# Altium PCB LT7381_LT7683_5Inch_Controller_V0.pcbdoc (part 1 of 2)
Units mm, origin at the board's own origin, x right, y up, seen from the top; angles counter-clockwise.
Board outline 60 x 56 mm, 2 copper layers (Top Layer, Bottom Layer); 80 components, 113 nets, 434 pads, 201 vias.
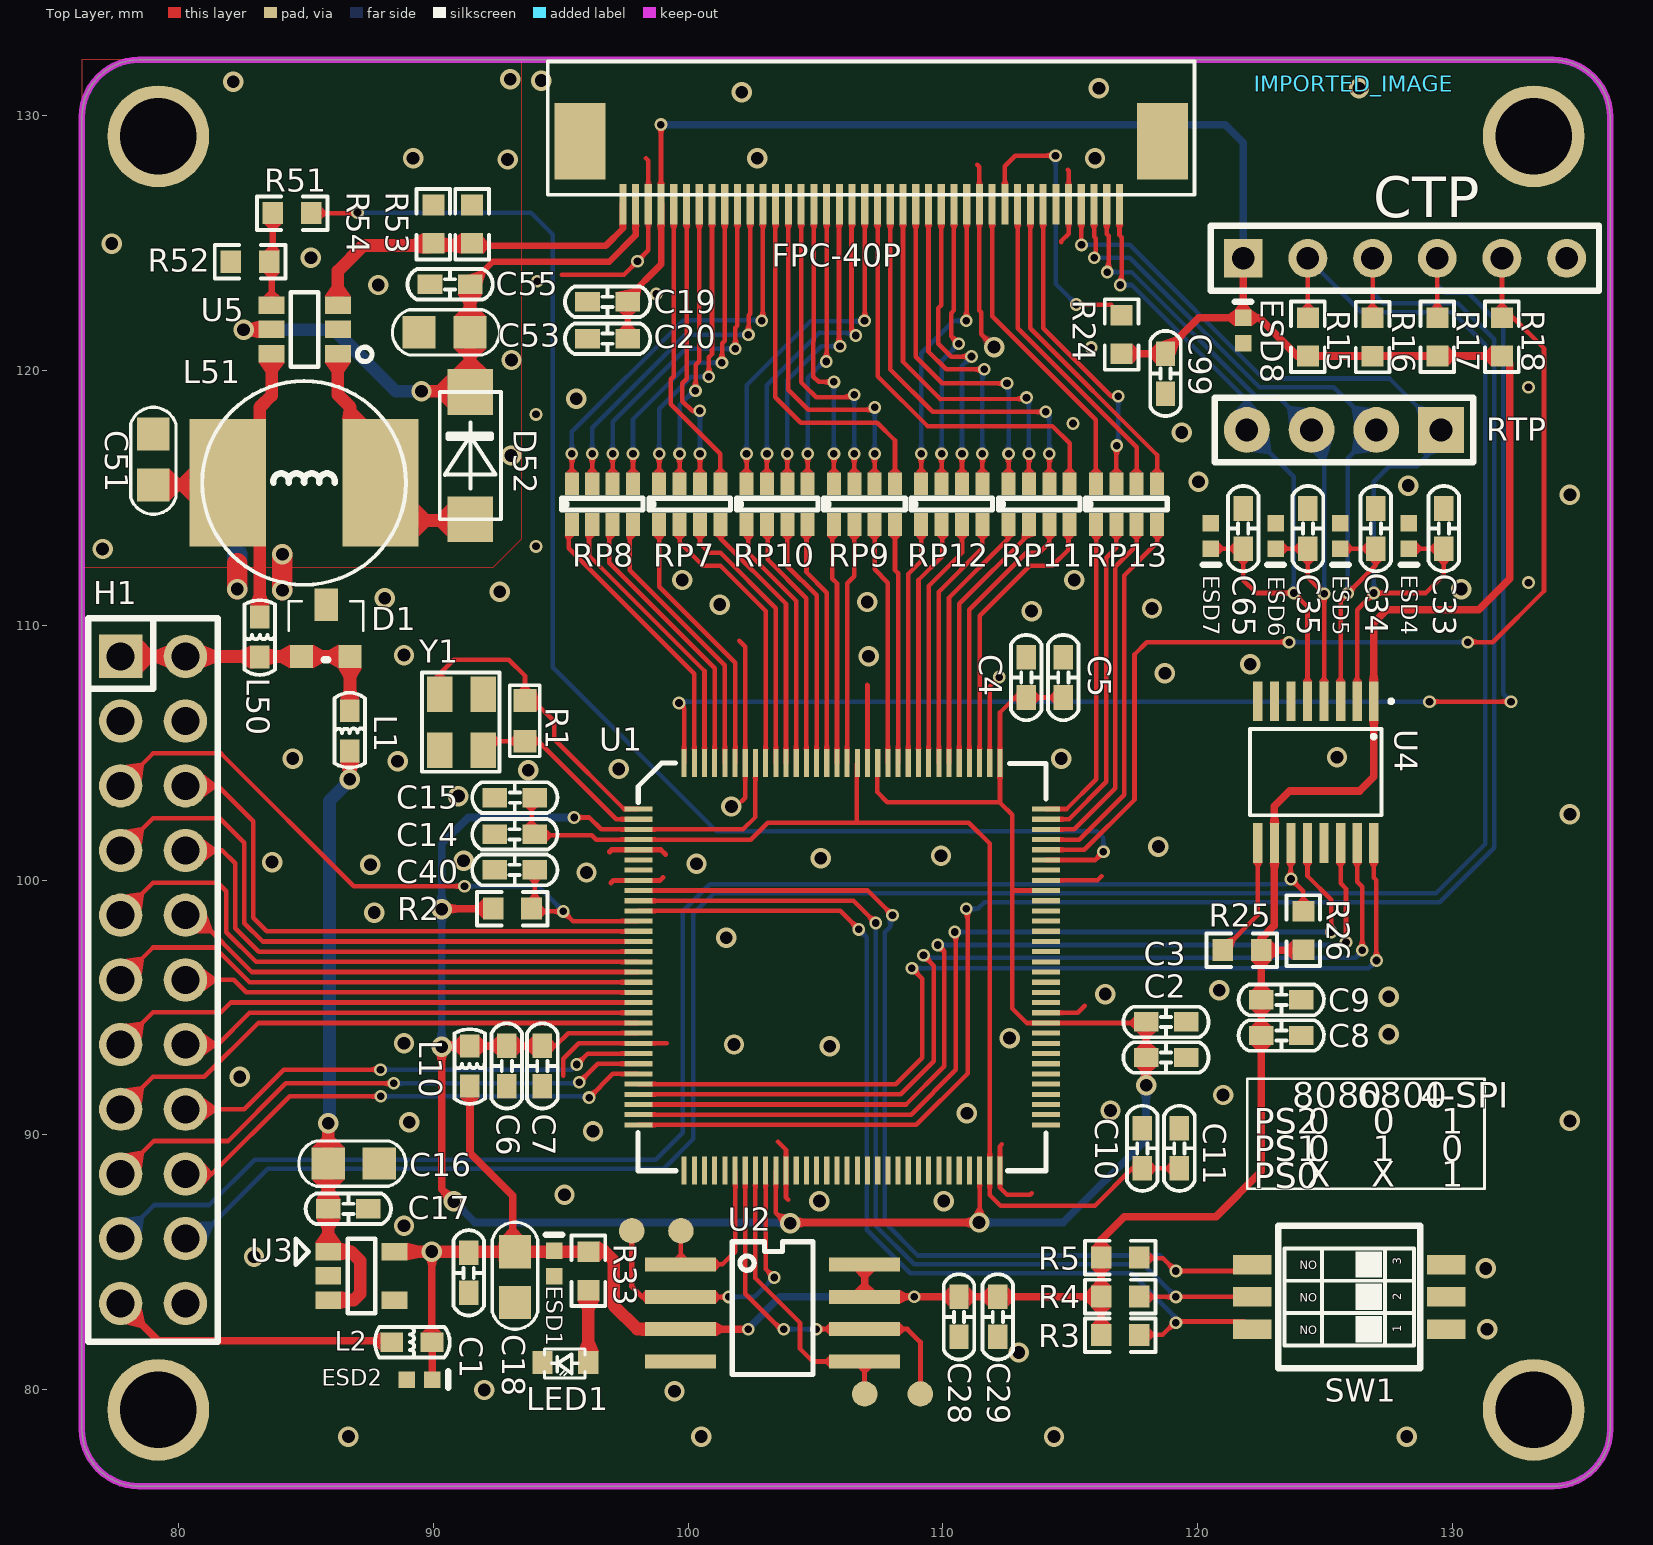
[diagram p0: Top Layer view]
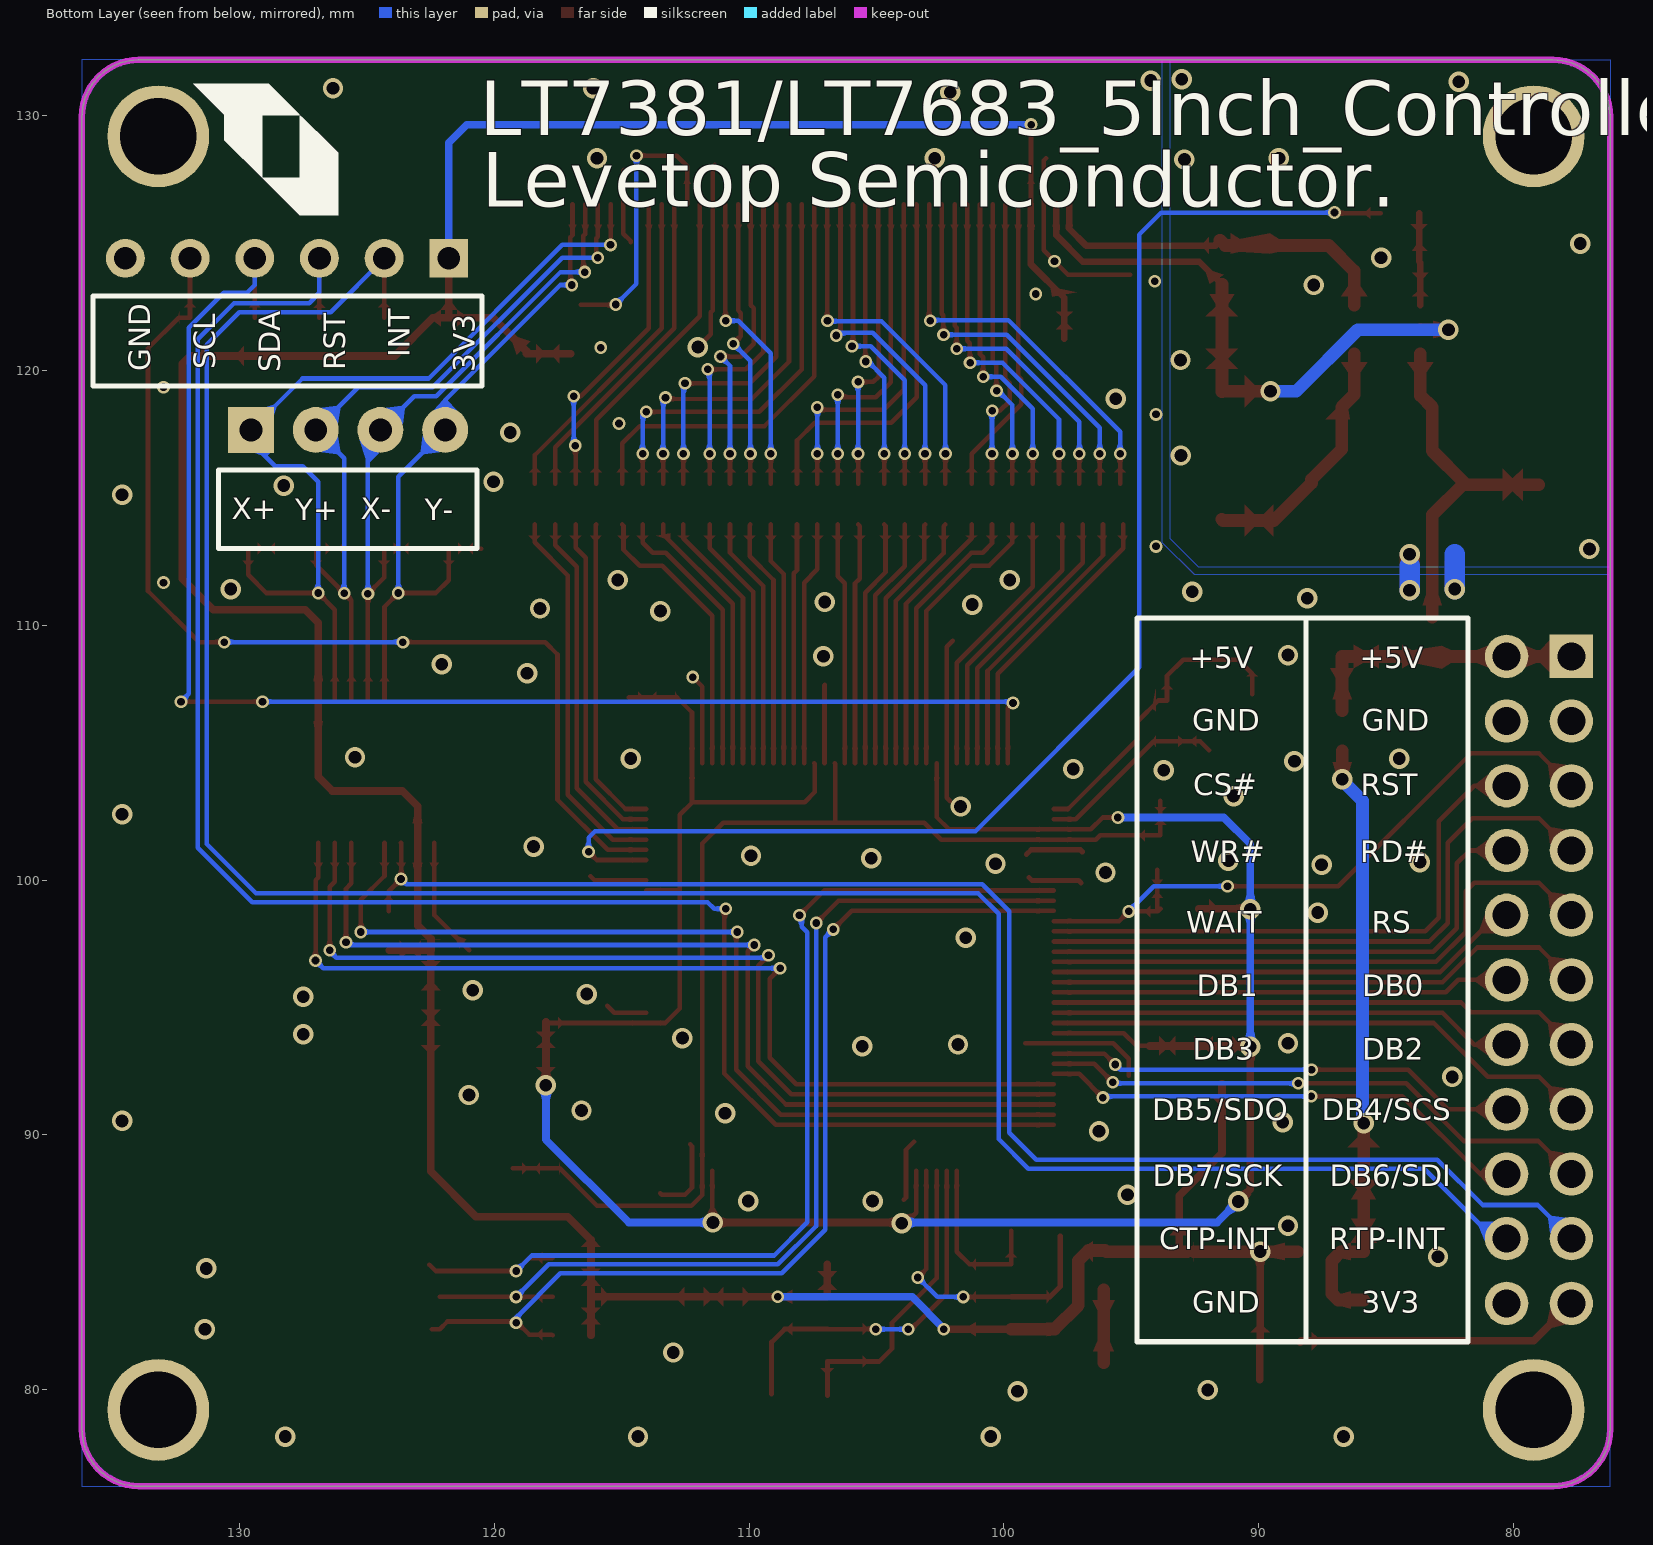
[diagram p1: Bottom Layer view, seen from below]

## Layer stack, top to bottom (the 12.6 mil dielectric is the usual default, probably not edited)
Top Layer: signal copper (thickness not stored)
Dielectric: dielectric 0.32, FR-4, Dk 4.8
Bottom Layer: signal copper (thickness not stored)

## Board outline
78.44,132.2 133.96,132.2 cw(c133.96,129.96) 136.2,129.96 136.2,78.44 cw(c133.96,78.44) 133.96,76.2 78.44,76.2 cw(c78.44,78.44) 76.2,78.44 76.2,129.96 cw(c78.44,129.96)

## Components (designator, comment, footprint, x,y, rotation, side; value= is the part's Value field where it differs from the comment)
C1 "1uF" C0603 91.389,85.362 r270 top
C2 "1uF" C0603 117.983,93.032 r0 top
C3 "0.1uf" C0603 117.983,94.429 r0 top
C4 "1uF" C0603 113.277,107.168 r90 top
C5 "0.1uf" C0603 114.731,107.168 r90 top
C6 "1uF" C0603 92.884,93.484 r270 top
C7 "0.1uf" C0603 94.281,93.484 r270 top
C8 "1uF" C0603 122.506,93.897 r0 top
C9 "0.1uF" C0603 122.506,95.294 r0 top
C10 "1uF" C0603 117.834,88.682 r90 top
C11 "0.1uf" C0603 119.288,88.682 r90 top
C14 "1uF" C0603 93.98,101.795 r180 top
C15 "0.1uf" C0603 93.981,103.236 r180 top
C16 "10uF" C0805 85.87,88.881 r0 top
C17 "1uF" C0603 85.878,87.092 r0 top
C18 "10uF" C0805 93.218,85.413 r270 top
C19 "1uF" C0603 97.625,122.7 r180 top
C20 "0.1uf" C0603 97.623,121.251 r180 top
C28 "1uF" C0603 110.638,83.634 r270 top
C29 "0.1uf" C0603 112.162,83.634 r270 top
C33 "20pF" C0603 129.669,113.014 r90 top
C34 "20pF" C0603 127.002,113.014 r90 top
C35 "20pF" C0603 124.335,113.014 r90 top
C40 "1uF" C0603 93.978,100.397 r180 top
C51 "22uF/50V" C0805_1 78.994,115.511 r90 top
C53 "22uF/50V" C0805_1 91.441,121.489 r180 top
C55 "0.1uF/50V" C0603 91.44,123.385 r180 top
C65 "20pF" C0603 121.795,113.014 r90 top
C99 "1uF" C0603 118.745,120.667 r270 top
CTP "HDR_6P" SIP-6P 121.793,124.409 r0 top
D1 "MMBZ5V6A" SOT-23 84.836,108.78 r0 top
D52 "B340A" DO-214 91.44,116.654 r90 top
ESD1 "PESD0402MS05" ESD0402 94.742,84.448 r90 top
ESD2 "PESD0402MS05" ESD0402 88.951,80.384 r0 top
ESD4 "PESD0402MS05" ESD0402 128.295,114.012 r270 top
ESD5 "PESD0402MS05" ESD0402 125.605,114.012 r270 top
ESD6 "PESD0402MS05" ESD0402 123.065,114.012 r270 top
ESD7 "PESD0402MS05" ESD0402 120.525,114.012 r270 top
ESD8 "PESD0402MS05" ESD0402 121.793,121.074 r90 top
FPC-40P "COM40" FPC40-0.5 107.188,126.687 r0 top
H1 "HDR_2*11P_2.54" HDR-TH_22P-P2.54-V-M-R2-C11-S2.54 78.994,96.08 r270 top
IMPORTED_IMAGE "IMPORTED_IMAGE" IMPORTED_IMAGE 126.136,131.267 r0 top
L1 "BEAD 0603 600R&amp;100MHZ" L0603 86.716,105.86 r270 top
L2 "BEAD 0603 600R&amp;100MHZ" L0603 89.154,81.857 r180 top
L10 "BEAD 0603 600R&amp;100MHZ" L0603 91.423,92.699 r90 top
L50 "BEAD 0603 600R&amp;100MHZ" L0603 83.185,109.542 r90 top
L51 "10uH 1A" IND8A 84.916,115.589 r0 top
LED1 "LED_1" 0603LED 96.085,81.056 r180 top
R1 "1M" R0603_1 93.597,107.049 r270 top
R2 "120R" R0603 93.1,98.874 r180 top
R3 "10K" R0603 116.967,82.129 r180 top
R4 "10K" R0603 116.967,83.648 r180 top
R5 "10K" R0603 116.967,85.177 r180 top
R15 "10K" R0603 124.333,121.328 r90 top
R16 "10K" R0603 126.873,121.32 r90 top
R17 "10K" R0603 129.413,121.328 r90 top
R18 "10K" R0603 131.953,121.328 r90 top
R24 "10K" R0603 117.018,121.418 r90 top
R25 "0R" R0603 121.742,97.245 r0 top
R26 "10K" R0603 124.155,98.016 r90 top
R33 "4.7K" R0603 96.085,84.656 r90 top
R51 "100R" R0603 84.455,126.179 r180 top
R52 "10K" R0603 82.804,124.274 r180 top
R53 "12R" R0603 89.996,125.749 r90 top
R54 "12R" R0603 91.52,125.749 r90 top
RP7 "RP4" 8R4R 100.076,114.749 r90 top
RP8 "RP4" 8R4R 96.647,114.749 r90 top
RP9 "RP4" 8R4R 106.934,114.749 r90 top
RP10 "RP4" 8R4R 103.505,114.749 r90 top
RP11 "RP4" 8R4R 113.792,114.749 r90 top
RP12 "RP4" 8R4R 110.363,114.749 r90 top
RP13 "RP4" 8R4R 117.221,114.749 r90 top
RTP "CON4" SIP-4P 129.558,117.67 r180 top
SW1 "DSHP03TSGET" SW-SMD_6P-L5.4-W5.4-P1.27-LS8.4 125.959,83.634 r90 top
U1 "LT768-136" LQFP128L 106.045,96.588 r90 top
U2 "XT25F128B/W25Q128B" SOP-8A 100.457,84.904 r0 top
U3 "HP5013 3-2" SOT23-5 85.879,85.417 r270 top
U4 "TSC2046" TSSOP-16_L5.0-W4.4-P0.65-LS6.4-BL-1 124.644,104.238 r180 top
U5 "HP2302D" SOT23-6 83.646,122.574 r90 top
Y1 "10M" M3225_1 91.95,105.099 r90 top

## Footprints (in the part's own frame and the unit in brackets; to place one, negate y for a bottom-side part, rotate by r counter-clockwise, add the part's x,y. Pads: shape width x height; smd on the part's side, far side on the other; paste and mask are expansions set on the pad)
8R4R [mm]
  rect 0.9x0.55 smd mask+0.102: 1(-0.79,1.209) 2(-0.79,0.409) 3(-0.79,-0.391) 4(-0.79,-1.191) 5(0.81,-1.191) 6(0.81,-0.391) 7(0.81,0.409) 8(0.81,1.209)
  silkscreen extent -0.22,-1.59 0.24,1.61
0603LED [mm]
  rect 0.8x0.9 smd mask+0.102: 1(0,0) 2(1.8,0)
  silkscreen extent 0.13,-0.53 1.73,0.6
C0603 [mil]
  rect 38x30 smd mask+4: 1(-0.09,-0.02) 2(61.91,-0.02)
  silkscreen extent -35,-24 97,24
C0805 [mm]
  rect 1.3x1.27 smd mask+0.102: 1(0.005,-0.011) 2(2.005,-0.011)
  silkscreen extent -1.15,-0.9 3.05,0.88
C0805_1 [mm]
  rect 1.3x1.27 smd mask+0.102: 1(0.005,-0.011) 2(2.005,-0.011)
  silkscreen extent -1.15,-0.9 3.05,0.88
DO-214 [mm]
  rect 1.8x1.8 smd mask+0.102: 1(-2.488,-0.011) 2(2.512,-0.011)
  silkscreen extent -2.49,-1.21 2.51,1.19
ESD0402 [mm]
  rect 0.65x0.65 smd mask+0.102: 1(1,0) 2(0,0)
  silkscreen extent 1.63,-0.32 1.63,0.33
FPC40-0.5 [mm]
  rect 0.28x1.6 smd mask+0.102: 1(-9.75,-0.159) 2(-9.25,-0.159) 3(-8.75,-0.159) 4(-8.25,-0.159) 5(-7.75,-0.159) 6(-7.25,-0.159) 7(-6.75,-0.159) 8(-6.25,-0.159) 9(-5.75,-0.159) 10(-5.25,-0.159) 11(-4.75,-0.159) 12(-4.25,-0.159) 13(-3.75,-0.159) 14(-3.25,-0.159) 15(-2.75,-0.159) 16(-2.25,-0.159) 17(-1.75,-0.159) 18(-1.25,-0.159) 19(-0.75,-0.159) 20(-0.25,-0.159) 21(0.25,-0.159) 22(0.75,-0.159) 23(1.25,-0.159) 24(1.75,-0.159) 25(2.25,-0.159) 26(2.75,-0.159) 27(3.25,-0.159) 28(3.75,-0.159) 29(4.25,-0.159) 30(4.75,-0.159) 31(5.25,-0.159) 32(5.75,-0.159) 33(6.25,-0.159) 34(6.75,-0.159) 35(7.25,-0.159) 36(7.75,-0.159) 37(8.25,-0.159) 38(8.75,-0.159) 39(9.25,-0.159) 40(9.75,-0.159)
  rect 2x3 smd mask+0.102: 41(-11.44,2.316) 42(11.44,2.316)
  silkscreen extent -12.7,0.22 12.7,5.45
HDR-TH_22P-P2.54-V-M-R2-C11-S2.54 [mm]
  rect 1.7x1.7 hole 1.1 paste+0 mask+0.051: 1(-12.7,-1.27)
  round 1.7 hole 1.1 paste+0 mask+0.051: 2(-12.7,1.27) 3(-10.16,-1.27) 4(-10.16,1.27) 5(-7.62,-1.27) 6(-7.62,1.27) 7(-5.08,-1.27) 8(-5.08,1.27) 9(-2.54,-1.27) 10(-2.54,1.27) 11(0,-1.27) 12(0,1.27) 13(2.54,-1.27) 14(2.54,1.27) 15(5.08,-1.27) 16(5.08,1.27) 17(7.62,-1.27) 18(7.62,1.27) 19(10.16,-1.27) 20(10.16,1.27) 21(12.7,-1.27) 22(12.7,1.27)
  silkscreen extent -14.2,-2.54 14.2,2.54
IMPORTED_IMAGE [mm]
IND8A [mm]
  rect 3x5 smd mask+0.102: 1(-2.992,0.003) 2(3.008,0.003)
  silkscreen extent -3.99,-4 4.01,4
L0603 [mil]
  rect 35.43x30 smd mask+4: 1(-31,0) 2(31,0)
  silkscreen extent -59,-24 57,24
LQFP128L [mm]
  rect 0.2x1.1 smd paste+0 mask+0.102: 1(6.2,8) 2(5.8,8) 3(5.4,8) 4(5,8) 5(4.6,8) 6(4.2,8) 7(3.8,8) 8(3.4,8) 9(3,8) 10(2.6,8) 11(2.2,8) 12(1.8,8) 13(1.4,8) 14(1,8) 15(0.6,8) 16(0.2,8) 17(-0.2,8) 18(-0.6,8) 19(-1,8) 20(-1.4,8) 21(-1.8,8) 22(-2.2,8) 23(-2.6,8) 24(-3,8) 25(-3.4,8) 26(-3.8,8) 27(-4.2,8) 28(-4.6,8) 29(-5,8) 30(-5.4,8) 31(-5.8,8) 32(-6.2,8) 65(-6.2,-8) 66(-5.8,-8) 67(-5.4,-8) 68(-5,-8) 69(-4.6,-8) 70(-4.2,-8) 71(-3.8,-8) 72(-3.4,-8) 73(-3,-8) 74(-2.6,-8) 75(-2.2,-8) 76(-1.8,-8) 77(-1.4,-8) 78(-1,-8) 79(-0.6,-8) 80(-0.2,-8) 81(0.2,-8) 82(0.6,-8) 83(1,-8) 84(1.4,-8) 85(1.8,-8) 86(2.2,-8) 87(2.6,-8) 88(3,-8) 89(3.4,-8) 90(3.8,-8) 91(4.2,-8) 92(4.6,-8) 93(5,-8) 94(5.4,-8) 95(5.8,-8) 96(6.2,-8)
  rect 1.1x0.2 smd paste+0 mask+0.102: 33(-8,6.2) 34(-8,5.8) 35(-8,5.4) 36(-8,5) 37(-8,4.6) 38(-8,4.2) 39(-8,3.8) 40(-8,3.4) 41(-8,3) 42(-8,2.6) 43(-8,2.2) 44(-8,1.8) 45(-8,1.4) 46(-8,1) 47(-8,0.6) 48(-8,0.2) 49(-8,-0.2) 50(-8,-0.6) 51(-8,-1) 52(-8,-1.4) 53(-8,-1.8) 54(-8,-2.2) 55(-8,-2.6) 56(-8,-3) 57(-8,-3.4) 58(-8,-3.8) 59(-8,-4.2) 60(-8,-4.6) 61(-8,-5) 62(-8,-5.4) 63(-8,-5.8) 64(-8,-6.2) 97(8,-6.2) 98(8,-5.8) 99(8,-5.4) 100(8,-5) 101(8,-4.6) 102(8,-4.2) 103(8,-3.8) 104(8,-3.4) 105(8,-3) 106(8,-2.6) 107(8,-2.2) 108(8,-1.8) 109(8,-1.4) 110(8,-1) 111(8,-0.6) 112(8,-0.2) 113(8,0.2) 114(8,0.6) 115(8,1) 116(8,1.4) 117(8,1.8) 118(8,2.2) 119(8,2.6) 120(8,3) 121(8,3.4) 122(8,3.8) 123(8,4.2) 124(8,4.6) 125(8,5) 126(8,5.4) 127(8,5.8) 128(8,6.2)
  silkscreen extent -8,-8.01 8,8.01
M3225_1 [mm]
  rect 1.4x1 smd mask+0.102: 1(0,0) 2(2.2,0) 3(2.2,1.7) 4(0,1.7)
  silkscreen extent -0.85,-0.65 3.05,2.4
R0603 [mm]
  rect 0.806x0.864 smd paste-100 mask+0.051: 1(-0.753,0) 2(0.753,0)
  silkscreen extent -1.39,-0.66 1.39,0.66
R0603_1 [mm]
  rect 0.9x0.9 smd mask+0.102: 1(0,0) 2(1.6,0)
  silkscreen extent -0.6,-0.6 2.2,0.58
SIP-4P [mm]
  rect 1.8x1.8 hole 0.889 mask+0.102: 1(0,0)
  round 1.8 hole 0.889 mask+0.102: 2(2.54,0) 3(5.08,0) 4(7.62,0)
  silkscreen extent -1.27,-1.27 8.89,1.27
SIP-6P [mil]
  rect 60x60 hole 35 mask+4: 1(0,0)
  round 60 hole 35 mask+4: 2(100,0) 3(200,0) 4(300,0) 5(400,0) 6(500,0)
  silkscreen extent -50,-50 550,50
SOP-8A [mm]
  rect 2.778x0.55 smd mask+0.102: 1(-0.75,0.005) 2(-0.75,-1.265) 3(-0.75,-2.535) 4(-0.75,-3.805) 5(6.473,-3.805) 6(6.473,-2.535) 7(6.473,-1.265) 8(6.473,0.005)
  silkscreen extent 1.27,-4.31 4.45,0.89
SOT23-5 [mil]
  rect 27x40 smd mask+4: 1(0.28,-0.14) 2(37.68,-0.14) 3(75.08,-0.14) 4(75.08,102.22) 5(0.28,102.22)
  silkscreen extent -20,-50 95,73
SOT23-6 [mil]
  rect 27x40 smd mask+4: 1(-75.07,-102.5) 2(-37.67,-102.5) 3(-0.27,-102.5) 4(-0.27,-0.14) 5(-37.67,-0.14) 6(-75.07,-0.14)
  silkscreen extent -95,-155 20,-30
SOT-23 [mil]
  rect 36x36 smd mask+4: 1(-0.41,-0.04) 2(74.59,-0.04)
  rect 36x50 smd mask+4: 3(37.59,79.96)
  silkscreen extent -20,-5 95,85
SW-SMD_6P-L5.4-W5.4-P1.27-LS8.4 [mil]
  rect 30x60 smd paste+0 mask+2: 1(-50,-150) 2(0,-150) 3(50,-150) 4(50,150) 5(0,150) 6(-50,150)
  silkscreen extent -110,-110 110,110
TSSOP-16_L5.0-W4.4-P0.65-LS6.4-BL-1 [mm]
  rect 0.364x1.56 smd paste+0 mask+0.051: 1(-2.275,-2.78) 2(-1.625,-2.78) 3(-0.975,-2.78) 4(-0.325,-2.78) 5(0.325,-2.78) 6(0.975,-2.78) 7(1.625,-2.78) 8(2.275,-2.78) 9(2.275,2.78) 10(1.625,2.78) 11(0.975,2.78) 12(0.325,2.78) 13(-0.325,2.78) 14(-0.975,2.78) 15(-1.625,2.78) 16(-2.275,2.78)
  silkscreen extent -3.03,-2.85 2.58,1.7

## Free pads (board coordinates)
  round 4 hole 3 mask+0.102: 1(79.2,79.2) 2(133.2,79.2) 3(133.2,129.2) 4(79.2,129.2)
  round 1 smd mask+0.102: TP4(109.118,79.825) TP5(106.934,79.825) TP6(99.72,86.226) TP7(97.79,86.226)

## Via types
v1: diameter 0.5, hole 0.3, Top Layer to Bottom Layer, 104 vias
v2: diameter 0.8, hole 0.5, Top Layer to Bottom Layer, 97 vias

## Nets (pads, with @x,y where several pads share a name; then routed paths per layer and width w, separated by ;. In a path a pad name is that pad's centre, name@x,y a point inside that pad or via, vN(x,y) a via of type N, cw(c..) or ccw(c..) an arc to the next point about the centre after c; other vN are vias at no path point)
$1N16243: R51.2 R52.1 U5.4 | length 3.6
  Top Layer w0.254: U5.4@83.65,122.567 83.65,124.24 83.702,124.291 R51.2@83.702,126.179
$1N16244: C51.1 L50.2 L51.1 U5.6 | length 14.5
  Top Layer w0.5: C51.1@79.005,115.516 81.848,115.516 L51.1@81.924,115.592 ; L50.2@83.185,110.329 83.185,114.331 L51.1@81.924,115.592 ; U5.6@83.65,120.667 83.65,119.024 83.185,118.559 83.185,116.853 L51.1@81.924,115.592
$1N16251: D52.1 L51.2 U5.1 | length 9.9
  Top Layer w0.5: U5.1@86.25,120.667 86.25,119.05 86.741,118.559 86.741,116.908 87.924,115.725 L51.2@87.924,115.592 89.402,114.114 91.399,114.114 D52.1@91.451,114.166
$1N48183: U4.13
$1N48192: R25.1 U4.9 | length 4.8
  Top Layer w0.18: R25.1@120.989,97.245 122.369,98.625 U4.9@122.369,101.458
$1N53057: LED1.1 R33.1 | length 2.8
  Top Layer w0.5: LED1.1@96.085,81.056 R33.1@96.085,83.903
+5V: C16.1 C17.1 L1.2 U3.1 U3.3 | length 24.1
  Top Layer w0.5: U3.3@85.875,83.51 86.879,83.51 87.125,83.756 87.125,85.056 86.771,85.41 U3.1@85.875,85.41 C17.1@85.875,87.091 C16.1@85.875,88.87 v2(85.875,90.456) ; v2(86.716,103.955) L1.2@86.716,105.073
  Bottom Layer w0.5: v2(85.875,90.456) 85.925,90.506 85.925,103.114 86.716,103.904 v2(86.716,103.955)
B0: FPC-40P.21 RP11.5 | length 17
  Top Layer w0.18: FPC-40P.21@107.438,126.528 107.438,119.784 109.399,117.824 114.3,117.824 114.983,117.141 RP11.5@114.983,115.559
B1: FPC-40P.22 RP11.6 | length 16.2
  Top Layer w0.18: FPC-40P.22@107.938,126.528 107.938,120.043 109.599,118.382 v1(114.046,118.382) ; RP11.6@114.183,115.559 v1(114.183,116.733)
  Bottom Layer w0.18: v1(114.046,118.382) 114.183,118.246 v1(114.183,116.733)
B2: FPC-40P.23 RP11.7 | length 15.1
  Top Layer w0.18: FPC-40P.23@108.438,126.528 108.438,120.343 109.897,118.884 113.234,118.893 v1@113.284,118.943 ; RP11.7@113.383,115.559 v1(113.383,116.733)
  Bottom Layer w0.18: v1(113.284,118.941) 113.383,118.842 v1(113.383,116.733)
B3: FPC-40P.24 RP11.8 | length 14
  Top Layer w0.18: FPC-40P.24@108.938,126.528 108.938,120.543 109.981,119.5 v1(112.522,119.5) ; RP11.8@112.583,115.559 v1(112.583,116.733)
  Bottom Layer w0.18: v1(112.522,119.5) 112.583,119.439 v1(112.583,116.733)
B4: FPC-40P.25 RP12.5 | length 12.8
  Top Layer w0.18: FPC-40P.25@109.438,126.528 109.438,120.743 110.135,120.046 111.615,120.046 v1(111.625,120.056) ; RP12.5@111.554,115.559 v1(111.554,116.733)
  Bottom Layer w0.18: v1(111.554,116.733) 111.554,119.985 v1(111.625,120.056)
B5: FPC-40P.26 RP12.6 | length 12.2
  Top Layer w0.18: FPC-40P.26@109.938,126.528 109.938,122.569 109.825,122.456 109.825,121.056 110.335,120.546 111.115,120.546 v1(111.125,120.556) ; RP12.6@110.754,115.559 v1(110.754,116.733)
  Bottom Layer w0.18: v1(110.754,116.733) 110.754,120.185 v1(111.125,120.556)
B6: FPC-40P.27 RP12.7 | length 11.4
  Top Layer w0.18: RP12.7@109.954,115.559 v1(109.954,116.733) ; FPC-40P.27@110.438,126.528 110.438,122.369 110.325,122.256 110.325,121.356 v1(110.625,121.056)
  Bottom Layer w0.18: v1(109.954,116.733) 109.954,120.385 v1(110.625,121.056)
B7: FPC-40P.28 RP12.8 | length 12
  Top Layer w0.18: RP12.8@109.154,115.559 v1(109.154,116.733) ; v1(110.925,121.956) 110.938,121.969 FPC-40P.28@110.938,126.528
  Bottom Layer w0.18: v1(109.154,116.733) 109.154,120.685 110.425,121.956 v1(110.925,121.956)
CTP_INT: CTP.2 H1.20 R15.2 | length 92.9
  Top Layer w0.18: R15.2@124.333,122.081 CTP.2@124.333,124.401
  Bottom Layer w0.18: H1.20@80.264,85.92 80.747,85.92 83.496,88.669 99.041,88.669 100.203,89.832 100.203,98.671 101.016,99.484 129.362,99.484 131.293,101.414 131.293,121.023 130.018,122.298 126.436,122.298 CTP.2@124.333,124.401
CTP_RST: CTP.3 R16.2 U1.32 | length 71.1
  Top Layer w0.18: U1.32@98.045,90.388 108.957,90.388 110.975,92.406 110.975,98.821 v1(110.922,98.874) ; R16.2@126.873,122.073 CTP.3@126.873,124.401
  Bottom Layer w0.18: v1(110.922,98.874) 111.379,98.874 111.639,99.134 129.507,99.134 131.648,101.275 131.648,121.226 130.226,122.648 127.279,122.648 126.873,123.055 CTP.3@126.873,124.401
CTP_SCL: CTP.5 R18.2 U1.92 | length 41.1
  Top Layer w0.18: U1.92@114.045,101.188 115.557,101.188 117.525,103.156 117.525,108.857 118.008,109.34 v1(123.596,109.34) ; v1(130.607,109.34) 131.599,109.34 133.604,111.345 133.604,120.872 132.395,122.081 R18.2@131.953,122.081 CTP.5@131.953,124.401
  Bottom Layer w0.18: v1(123.596,109.34) v1(130.607,109.34)
CTP_SDA: CTP.4 R17.2 U1.128 | length 56.6
  Top Layer w0.18: v1(99.644,106.951) 99.845,106.75 U1.128@99.845,104.588 ; v1(129.108,107.002) v1(132.309,107.002) ; R17.2@129.413,122.081 CTP.4@129.413,124.401
  Bottom Layer w0.18: v1(99.644,106.951) 99.695,107.002 v1(129.108,107.002) ; CTP.4@129.413,124.401 129.413,123.36 129.718,123.055 130.632,123.055 132.004,121.683 132.004,107.307 v1(132.309,107.002)
DE: FPC-40P.34 RP13.7 | length 12.4
  Top Layer w0.18: FPC-40P.34@113.938,126.528 113.938,121.664 116.61,118.992 v1(116.891,118.992) ; RP13.7@116.812,115.559 v1@116.812,117.043
  Bottom Layer w0.18: v1(116.825,117.056) 116.891,117.122 v1(116.891,118.992)
FLASH_SPI_CS0: U1.37
FLASH_SPI_CS1: pad.TP6 U1.38 U2.1 | length 6.9
  Top Layer w0.18: pad.TP6@99.72,86.226 99.72,84.922 U2.1@99.707,84.909 101.351,84.909 101.854,85.412 101.854,88.579 U1.38@101.845,88.588
FLASH_SPI_SCLK: pad.TP4 U1.39 U2.6 | length 14.5
  Top Layer w0.18: U1.39@102.245,88.588 102.245,83.751 103.632,82.364 v1(103.759,82.364) ; v1(105.029,82.364) 105.034,82.369 U2.6@106.93,82.369
  Top Layer w0.2: U2.6@106.93,82.369 108.607,82.369 109.118,81.857 pad.TP4@109.118,79.825
  Bottom Layer w0.18: v1(103.759,82.364) v1(105.029,82.364)
FLASH_SPI_SI: pad.TP5 U1.40 U2.5 | length 11.8
  Top Layer w0.18: U1.40@102.645,88.588 102.645,84.367 104.394,82.618 104.394,81.602 104.897,81.099 U2.5@106.93,81.099
  Top Layer w0.2: U2.5@106.93,81.099 106.934,81.095 pad.TP5@106.934,79.774
FLASH_SPI_SO: pad.TP7 U1.41 U2.2 | length 12.4
  Top Layer w0.18: U2.2@99.707,83.639 99.712,83.634 v1(101.6,83.634) ; U1.41@103.045,88.588 103.045,84.729 v1(103.378,84.396)
  Top Layer w0.2: pad.TP7@97.79,86.023 97.79,84.042 98.193,83.639 U2.2@99.707,83.639
  Bottom Layer w0.18: v1(101.6,83.634) 102.616,83.634 v1(103.378,84.396)
G0: FPC-40P.13 RP9.5 | length 14.7
  Top Layer w0.18: FPC-40P.13@103.438,126.528 103.425,126.515 103.425,118.956 104.425,117.956 107.425,117.956 108.125,117.256 RP9.5@108.125,115.559
G1: FPC-40P.14 RP9.6 | length 14
  Top Layer w0.18: FPC-40P.14@103.938,126.528 103.938,119.243 104.725,118.456 107.225,118.456 v1(107.325,118.556) ; RP9.6@107.325,115.559 v1(107.325,116.733)
  Bottom Layer w0.18: v1(107.325,116.733) v1(107.325,118.556)
G2: FPC-40P.15 RP9.7 | length 12.9
  Top Layer w0.18: FPC-40P.15@104.438,126.528 104.438,119.543 104.525,119.456 105.025,118.956 106.425,118.956 v1(106.525,119.056) ; RP9.7@106.525,115.559 v1(106.525,116.733)
  Bottom Layer w0.18: v1(106.525,116.733) v1(106.525,119.056)
G3: FPC-40P.16 RP9.8 | length 11.7
  Top Layer w0.18: FPC-40P.16@104.938,126.528 104.938,121.169 104.915,121.146 104.915,119.766 105.125,119.556 v1(105.725,119.556) ; RP9.8@105.725,115.559 v1(105.725,116.733)
  Bottom Layer w0.18: v1(105.725,116.733) v1(105.725,119.556)
G4: FPC-40P.17 RP10.5 | length 11.3
  Top Layer w0.18: RP10.5@104.696,115.559 v1(104.696,116.733) ; v1(105.425,120.356) 105.438,120.369 FPC-40P.17@105.438,126.528
  Bottom Layer w0.18: v1(104.696,116.733) 104.696,119.727 105.325,120.356 v1(105.425,120.356)
G5: FPC-40P.18 RP10.6 | length 12.4
  Top Layer w0.18: RP10.6@103.896,115.559 v1(103.896,116.733) ; FPC-40P.18@105.938,126.528 105.925,126.515 105.925,121.056 v1@106.025,120.956
  Bottom Layer w0.18: v1(103.896,116.733) 103.896,119.627 105.225,120.956 v1@106.025,120.956
  other v1: 105.963,120.956
G6: FPC-40P.19 RP10.7 | length 13.5
  Top Layer w0.18: RP10.7@103.096,115.559 v1(103.096,116.733) ; FPC-40P.19@106.438,126.528 106.415,126.505 106.415,121.566 106.578,121.403 v1(106.578,121.38)
  Bottom Layer w0.18: v1(103.096,116.733) 103.096,119.427 105.15,121.481 106.477,121.481 v1(106.578,121.38)
G7: FPC-40P.20 RP10.8 | length 14.1
  Top Layer w0.18: RP10.8@102.296,115.559 v1(102.296,116.733) ; v1(106.925,121.956) 106.938,121.969 FPC-40P.20@106.938,126.528
  Bottom Layer w0.18: v1(102.296,116.733) 102.296,119.427 104.807,121.938 106.907,121.938 v1(106.925,121.956)
GND: C1.2 C2.2 C3.2 C4.2 C5.2 C6.2 C7.2 C8.2 C9.2 C10.2 C11.2 C14.2 C15.2 C16.2 C17.2 C18.2 C19.2 C20.2 C28.2 C29.2 C33.2 C34.2 C35.2 C40.2 C51.2 C53.2 C55.2 C65.2 C99.2 CTP.6 D1.3 ESD1.2 ESD2.2 ESD4.2 ESD5.2 ESD6.2 ESD7.2 ESD8.2 FPC-40P.3 FPC-40P.29 FPC-40P.36 H1.3 H1.4 H1.22 LED1.2 pad.1 pad.2 pad.3 pad.4 R52.2 R53.2 R54.2 SW1.1 SW1.2 SW1.3 U1.5 U1.6 U1.7 U1.8 U1.24 U1.43 U1.64 U1.76 U1.89 U1.98 U1.110 U1.122 U2.4 U3.2 U4.6 U5.2 Y1.2 Y1.4 | length 54.5
  Top Layer w0.18: 95.047,123.767 97.485,123.767 v1(98.015,124.297) 98.438,124.72 FPC-40P.3@98.438,126.528 98.438,128.25 98.349,128.339 ; 95.098,92.322 95.098,92.982 95.703,93.588 U1.24@98.045,93.588 99.158,93.588 99.162,93.592 ; 102.006,109.391 102.245,109.152 U1.122@102.245,104.588 102.245,103.229 102.108,103.092 ; 103.53,89.731 103.845,89.417 U1.43@103.845,88.588 103.845,87.537 103.937,87.445 ; 107.036,107.664 107.045,107.654 U1.110@107.045,104.588 ; 111.354,128.085 111.438,128 FPC-40P.29@111.438,126.528 111.438,122.362 111.506,122.294 111.506,121.43 v2(112.014,120.922) ; U1.98@111.845,104.588 111.845,107.596 v1(112.217,107.968) ; 112.319,89.63 112.245,89.556 U1.64@112.245,88.588 112.245,87.925 112.522,87.648 113.436,87.648 113.487,87.699 ; U1.76@114.045,94.788 115.293,94.788 115.57,95.065 ; U1.89@114.045,99.988 116.073,99.988 116.23,100.145 ; 114.656,125.037 114.656,125.088 114.938,125.371 FPC-40P.36@114.938,126.528 114.938,127.853 114.91,127.882
  Top Layer w0.2: 96.926,101.11 97.004,101.188 U1.5@98.045,101.188 98.932,101.188 99.111,101.009 ; 96.977,99.891 97.074,99.988 U1.8@98.045,99.988 98.903,99.988 99.009,100.094
  Top Layer w0.8: v2(82.296,111.423) 82.296,112.439 ; v2(84.074,111.372) v2(84.074,112.794)
  Bottom Layer w0.8: v2(82.296,111.423) 82.296,112.794 ; v2(84.074,111.372) 84.074,112.337
  other v1: 132.994,111.677 94.031,113.099 115.113,117.925 94.031,118.281 132.994,119.348 115.824,120.904 98.755,123.005 94.082,123.513
  other v2: 86.665,78.149 100.516,78.149 114.368,78.149 128.219,78.149 99.466,79.927 91.999,79.978 112.979,81.451 131.369,82.365 131.318,84.753 82.956,85.21 88.849,86.429 105.156,87.394 110.033,87.394 95.148,87.648 96.266,90.138 89.052,90.493 134.62,90.544 110.947,90.849 116.586,90.95 121.006,91.56 82.398,92.271 105.562,93.472 101.803,93.541 88.849,93.592 112.624,93.795 127.508,93.948 127.508,95.421 116.383,95.522 120.853,95.675 101.498,97.739 87.681,98.723 96.012,100.298 87.528,100.602 100.33,100.635 83.668,100.704 91.186,100.755 105.207,100.856 109.931,100.958 118.466,101.314 134.62,102.584 101.702,102.888 90.983,103.295 93.726,104.311 97.282,104.362 88.595,104.666 84.48,104.768 114.656,104.768 125.476,104.819 118.72,108.121 122.072,108.476 107.086,108.781 88.849,108.832 113.487,110.559 118.212,110.661 101.244,110.813 107.036,110.915 88.087,111.067 92.608,111.321 130.353,111.423 99.771,111.778 115.164,111.778 77.013,112.998 134.62,115.131 128.27,115.487 120.04,115.639 93.051,116.666 119.38,117.57 95.606,118.89 93.066,120.414 87.833,123.361 85.192,124.428 77.368,124.986 92.913,128.288 89.205,128.339 102.718,128.339 115.976,128.339 102.108,130.93 116.129,131.082 126.34,131.082 82.144,131.336 94.234,131.387 93.015,131.438
HSYNC: FPC-40P.32 RP13.6 | length 12.9
  Top Layer w0.18: FPC-40P.32@112.938,126.528 112.938,121.664 117.612,116.99 RP13.6@117.612,115.559
LCD_B0: RP11.4 U1.99 | length 11.4
  Top Layer w0.18: U1.99@111.445,104.588 111.445,110.37 113.411,112.336 114.3,112.336 114.935,112.971 114.935,113.911 RP11.4@114.983,113.959
LCD_B1: RP11.3 U1.100 | length 11
  Top Layer w0.18: U1.100@111.045,104.588 111.045,110.605 113.284,112.844 113.792,112.844 114.183,113.235 RP11.3@114.183,113.959
LCD_B2: RP11.2 U1.101 | length 10.5
  Top Layer w0.18: U1.101@110.645,104.588 110.645,110.84 113.383,113.578 RP11.2@113.383,113.959
LCD_B3: RP11.1 U1.102 | length 10.3
  Top Layer w0.18: U1.102@110.245,104.588 110.245,111.075 112.583,113.413 RP11.1@112.583,113.959
LCD_B4: RP12.4 U1.103 | length 10.1
  Top Layer w0.18: U1.103@109.845,104.588 109.845,111.31 111.554,113.019 RP12.4@111.554,113.959
LCD_B5: RP12.3 U1.104 | length 9.9
  Top Layer w0.18: U1.104@109.445,104.588 109.445,111.545 110.754,112.854 RP12.3@110.754,113.959
LCD_B6: RP12.2 U1.105 | length 9.8
  Top Layer w0.18: U1.105@109.045,104.588 109.045,111.78 109.982,112.717 109.982,113.93 RP12.2@109.954,113.959
LCD_B7: RP12.1 U1.106 | length 9.6
  Top Layer w0.18: U1.106@108.645,104.588 108.645,112.015 109.154,112.524 RP12.1@109.154,113.959
LCD_DE: RP13.2 U1.95 | length 13.3
  Top Layer w0.18: U1.95@114.045,102.388 114.957,102.388 116.424,103.855 116.424,112.655 116.812,113.043 RP13.2@116.812,113.959
LCD_G0: RP9.4 U1.107 | length 9.4
  Top Layer w0.18: RP9.4@108.125,113.959 108.125,112.161 108.245,112.041 U1.107@108.245,104.588
LCD_G1: RP9.3 U1.108 | length 9.6
  Top Layer w0.18: RP9.3@107.325,113.959 107.325,112.199 107.845,111.679 U1.108@107.845,104.588
LCD_G2: RP9.2 U1.112 | length 9.5
  Top Layer w0.18: U1.112@106.245,104.588 106.245,111.647 106.525,111.927 RP9.2@106.525,113.959
LCD_G3: RP9.1 U1.113 | length 9.5
  Top Layer w0.18: RP9.1@105.725,113.959 105.664,113.898 105.664,111.828 105.845,111.647 U1.113@105.845,104.588
LCD_G4: RP10.4 U1.114 | length 9.7
  Top Layer w0.18: RP10.4@104.696,113.959 104.648,113.911 104.648,112.082 105.445,111.285 U1.114@105.445,104.588
LCD_G5: RP10.3 U1.115 | length 9.8
  Top Layer w0.18: RP10.3@103.896,113.959 103.896,112.324 105.045,111.175 U1.115@105.045,104.588
LCD_G6: RP10.2 U1.116 | length 10
  Top Layer w0.18: RP10.2@103.096,113.959 103.124,113.93 103.124,112.586 104.645,111.065 U1.116@104.645,104.588
LCD_G7: RP10.1 U1.117 | length 10.2
  Top Layer w0.18: RP10.1@102.296,113.959 102.362,113.892 102.362,112.838 104.245,110.955 U1.117@104.245,104.588
LCD_HSYNC: RP13.3 U1.94 | length 14.1
  Top Layer w0.18: U1.94@114.045,101.988 115.157,101.988 116.775,103.605 116.775,112.305 117.612,113.143 RP13.3@117.612,113.959
LCD_PCLK: RP13.1 U1.96 | length 12.5
  Top Layer w0.18: U1.96@114.045,102.788 114.857,102.788 116.025,103.956 116.025,113.945 RP13.1@116.012,113.959
LCD_R0: RP7.4 U1.118 | length 10.4
  Top Layer w0.18: RP7.4@101.267,113.959 101.267,113.423 103.845,110.845 U1.118@103.845,104.588
LCD_R1: RP7.3 U1.119 | length 10.9
  Top Layer w0.18: RP7.3@100.467,113.959 100.467,113.215 100.838,112.844 101.275,112.844 103.445,110.674 U1.119@103.445,104.588
LCD_R2: RP7.2 U1.120 | length 11.2
  Top Layer w0.18: RP7.2@99.667,113.959 99.667,113.253 100.584,112.336 101.272,112.336 103.045,110.564 U1.120@103.045,104.588
LCD_R3: RP7.1 U1.123 | length 10.6
  Top Layer w0.18: RP7.1@98.867,113.959 98.867,111.517 101.854,108.53 101.854,104.597 U1.123@101.845,104.588
LCD_R4: RP8.4 U1.124 | length 10.9
  Top Layer w0.18: RP8.4@97.711,113.959 97.711,112.163 101.445,108.429 U1.124@101.445,104.588
LCD_R5: RP8.3 U1.125 | length 11.1
  Top Layer w0.18: RP8.3@96.911,113.959 96.911,112.453 101.045,108.319 U1.125@101.045,104.588
LCD_R6: RP8.2 U1.126 | length 11.2
  Top Layer w0.18: RP8.2@96.111,113.959 96.111,112.743 100.645,108.209 U1.126@100.645,104.588
LCD_R7: RP8.1 U1.127 | length 11.4
  Top Layer w0.18: RP8.1@95.311,113.959 95.311,113.033 100.245,108.099 U1.127@100.245,104.588
LCD_VSYNC: RP13.4 U1.93 | length 15
  Top Layer w0.18: U1.93@114.045,101.588 115.357,101.588 117.125,103.356 117.125,111.956 118.425,113.256 118.425,113.945 RP13.4@118.412,113.959
LDO_CAP12: C10.1 C11.1 C14.1 C15.1 U1.4 U1.63 U1.111 | length 44.4
  Top Layer w0.18: C15.1@93.857,103.11 93.857,101.756 96.225,101.756 96.393,101.588 U1.4@98.045,101.588 102.457,101.588 103.125,102.256 106.625,102.256 ; U1.111@106.645,104.588 106.625,104.568 106.625,102.256 ; C11.1@119.289,88.68 C10.1@117.835,88.68 117.441,88.68 115.974,87.213 112.268,87.213 111.845,87.636 U1.63@111.845,88.588 111.845,101.436 111.025,102.256 106.625,102.256
LEDA: C53.1 C55.1 D52.2 FPC-40P.2 U5.5 | length 23.7
  Top Layer w0.254: C55.1@91.442,123.386 92.331,124.274 96.901,124.274 97.938,125.311 FPC-40P.2@97.938,126.528
  Top Layer w0.5: v2(82.55,121.607) 83.64,121.607 U5.5@83.65,121.617 ; v2(89.535,119.194) 91.423,119.194 D52.2@91.442,119.175 ; C55.1@91.442,123.386 D52.2@91.442,119.175 ; D52.2@91.451,119.166 D52.2@91.442,119.175
  Bottom Layer w0.5: v2(82.55,121.607) 86.106,121.607 88.519,119.194 v2(89.535,119.194)
LEDK: FPC-40P.1 R53.1 R54.1 U5.3 | length 14.4
  Top Layer w0.254: R54.1@91.52,125.122 91.694,124.949 91.694,124.909 96.774,124.909 97.438,125.573 FPC-40P.1@97.438,126.528
  Top Layer w0.5: U5.3@86.25,122.567 86.25,123.91 87.249,124.909 91.307,124.909 R54.1@91.52,125.122
LT768_CS#: H1.6 U1.13 | length 22.4
  Top Layer w0.18: H1.6@80.264,103.7 81.534,103.7 82.931,102.303 82.931,98.518 83.464,97.985 98.042,97.985 U1.13@98.045,97.988
LT768_DB0: H1.11 U1.18 | length 21.4
  Top Layer w0.18: H1.11@77.724,96.08 78.994,97.35 81.419,97.35 82.781,95.988 U1.18@98.045,95.988
LT768_DB1: H1.12 U1.19 | length 18
  Top Layer w0.18: H1.12@80.264,96.08 82.169,96.08 82.661,95.588 U1.19@98.045,95.588
LT768_DB2: H1.13 U1.20 | length 21
  Top Layer w0.18: H1.13@77.724,93.54 78.994,94.81 81.661,94.81 82.042,95.191 98.042,95.191 U1.20@98.045,95.188
LT768_DB3: H1.14 U1.21 | length 18.3
  Top Layer w0.18: H1.14@80.264,93.54 81.534,93.54 82.782,94.788 U1.21@98.045,94.788
LT768_DB4_SCS#: H1.15 U1.22 | length 21.7
  Top Layer w0.18: H1.15@77.724,91 78.994,92.27 81.001,92.27 83.119,94.388 U1.22@98.045,94.388
LT768_DB5_SDO: H1.16 U1.25 | length 18.7
  Top Layer w0.18: H1.16@80.264,91 82.575,91 84.131,92.556 v1(87.925,92.556) ; v1(95.625,92.756) 96.057,93.188 U1.25@98.045,93.188
  Bottom Layer w0.18: v1(87.925,92.556) 95.425,92.556 v1(95.625,92.756)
